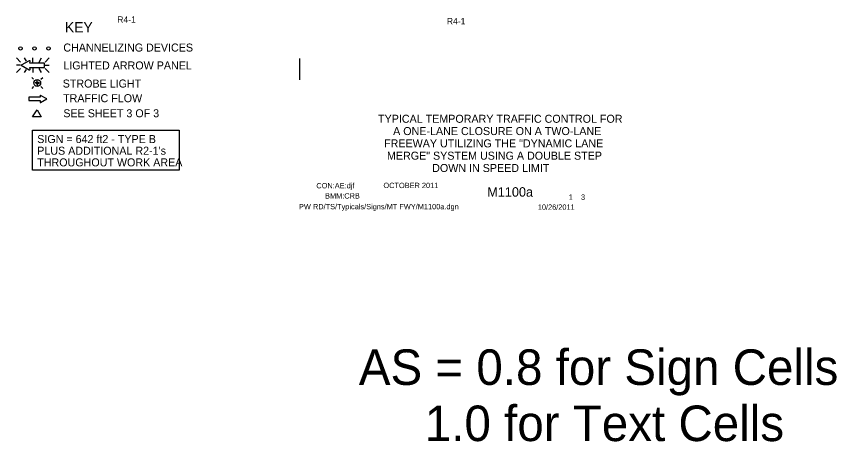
# Model space of a CAD drawing. Extents: x 15262 to 18126, y 1908 to 6555.
# Drawn here: x 15262 to 16214, y 1908 to 2402 of the extents above; entities that cross this region are included whole.
import ezdxf

# ---------------------------------------------------------------- set-up
doc = ezdxf.new("R2010")
doc.units = 0
for name, color, linetype in [('ALI_LEGAL_EX', 7, 'Continuous'), ('BORDER_SIGNAL_WO', 7, 'Continuous'), ('MT_SCRATCH_LEVEL_E', 7, 'Continuous'), ('TRAFFIC_SIGNS_PR', 7, 'Continuous'), ('TYPICAL_TEXT_DIMEN_EX', 7, 'Continuous'), ('TYPICAL_TEXT_DIMEN_PR', 7, 'Continuous')]:
    doc.layers.add(name, color=color, linetype=linetype)

msp = doc.modelspace()

# ---------------------------------------------------------------- linework, layer by layer
at = {"layer": 'ALI_LEGAL_EX'}
msp.add_lwpolyline([(15590.81, 2328.27), (15590.81, 2353.27)], dxfattribs=at)
at = {"layer": 'MT_SCRATCH_LEVEL_E'}
for p, q in [((15289.39, 2308.13), (15276.14, 2308.13)), ((15276.14, 2308.13), (15276.14, 2304.39)), ((15289.08, 2309.91), (15289.39, 2308.13)), ((15297, 2306.28), (15289.76, 2310.39)), ((15289.76, 2302.13), (15297, 2306.28)), ((15276.14, 2304.39), (15289.39, 2304.39)), ((15289.39, 2304.39), (15289.08, 2302.61))]:
    msp.add_line(p, q, dxfattribs=at)
for centre, start, end in [((15289.54, 2309.98), 60.42484, 189.96381), ((15289.54, 2302.54), 170.03619, 299.77312)]:
    msp.add_arc(centre, 0.463, start, end, dxfattribs=at)
at = {"layer": 'TRAFFIC_SIGNS_PR'}
for p, q in [((15261.64, 2353.83), (15266.58, 2348.9)), ((15273.41, 2350.01), (15271.2, 2353.84)), ((15280.73, 2348.9), (15280.73, 2353.84)), ((15287.96, 2348.9), (15290.81, 2353.84)), ((15294.88, 2348.9), (15299.81, 2353.84)), ((15266.58, 2345.35), (15261.64, 2345.35)), ((15294.88, 2345.35), (15299.81, 2345.35)), ((15261.64, 2336.86), (15266.58, 2341.79)), ((15271.16, 2336.85), (15273.27, 2340.52)), ((15280.73, 2341.79), (15280.73, 2336.85)), ((15290.86, 2336.85), (15288.01, 2341.79)), ((15294.88, 2341.79), (15299.81, 2336.85)), ((15281.6, 2329.06), (15279.56, 2331.09)), ((15285.88, 2324.78), (15283, 2324.78)), ((15285.88, 2324.78), (15285.88, 2327.66)), ((15285.88, 2324.78), (15285.88, 2320.84)), ((15285.88, 2324.78), (15288.76, 2324.78)), ((15290.16, 2329.06), (15292.19, 2331.09)), ((15281.6, 2320.5), (15279.56, 2318.47)), ((15292.19, 2318.47), (15290.16, 2320.5))]:
    msp.add_line(p, q, dxfattribs=at)
for points in [[(15276.65, 2350.62), (15267.36, 2345.35), (15276.66, 2340.02)], [(15277.53, 2340.65), (15277.13, 2342.92), (15294.14, 2342.92), (15294.14, 2347.72), (15277.13, 2347.72), (15277.53, 2350)]]:
    msp.add_lwpolyline(points, dxfattribs=at)
for centre, radius in [((15266.38, 2364.95), 2), ((15282.68, 2364.95), 2), ((15298.98, 2364.95), 2), ((15285.88, 2324.78), 3.94), ((15285.88, 2324.78), 1.28)]:
    msp.add_circle(centre, radius, dxfattribs=at)
for centre, radius, start, end in [((15276.94, 2350.1), 0.598, 350.73078, 118.89165), ((15276.94, 2340.55), 0.597, 241.48329, 9.95933)]:
    msp.add_arc(centre, radius, start, end, dxfattribs=at)
at = {"layer": 'TYPICAL_TEXT_DIMEN_EX'}
msp.add_lwpolyline([(15280.23, 2269.93), (15450.6, 2269.93), (15450.6, 2223.36), (15280.23, 2223.36)], close=True, dxfattribs=at)
at = {"layer": 'TYPICAL_TEXT_DIMEN_PR'}
msp.add_lwpolyline([(15280.34, 2285.58), (15285.8, 2293.46), (15290.42, 2285.58)], close=True, dxfattribs=at)

# ---------------------------------------------------------------- texts
at = {"layer": 'BORDER_SIGNAL_WO'}
for s, height, p in [('TYPICAL TEMPORARY TRAFFIC CONTROL FOR', 9.3, (15681.73, 2278.54)), ('A ONE-LANE CLOSURE ON A TWO-LANE', 9.3, (15699.24, 2264.24)), ('FREEWAY UTILIZING THE "DYNAMIC LANE', 9.3, (15688.74, 2249.94)), ('MERGE" SYSTEM USING A DOUBLE STEP ', 9.3, (15692.1, 2235.64)), ('DOWN IN SPEED LIMIT', 9.3, (15744.6, 2221.34)), ('CON:AE:djf  ', 6.2, (15610.05, 2202.35)), ('    OCTOBER 2011    ', 6.2, (15678.44, 2202.63)), ('    M1100a   ', 11, (15792.22, 2192.67)), ('BMM:CRB   ', 6.2, (15620.17, 2190.46)), (' 1    3 ', 6.2, (15900.81, 2188.99)), ('PW RD/TS/Typicals/Signs/MT FWY/M1100a.dgn      ', 6.2, (15589.92, 2178)), ('10/26/2011    ', 6.2, (15867.29, 2177.42)), ('AS = 0.8 for Sign Cells', 41.2877, (15659.37, 1973.92)), ('     1.0 for Text Cells', 41.2877, (15659.37, 1908.64))]:
    msp.add_text(s, height=height, dxfattribs=at).set_placement(p)
at = {"layer": 'TRAFFIC_SIGNS_PR'}
for p in [(15378.82, 2394.7), (15761.67, 2392.86)]:
    msp.add_text('R4-1', height=7.44, dxfattribs=at).set_placement(p)
at = {"layer": 'TYPICAL_TEXT_DIMEN_EX'}
for s, height, p in [('KEY', 12, (15318.11, 2383.5)), ('CHANNELIZING DEVICES', 9.3, (15316.16, 2361.28)), ('LIGHTED ARROW PANEL', 9.3, (15316.16, 2340.52)), ('STROBE LIGHT', 9.3, (15315.4, 2319.46)), ('TRAFFIC FLOW', 9.3, (15315.86, 2302.45)), ('SEE SHEET 3 OF 3', 9.3, (15316.16, 2284.93)), ('SIGN = 642 ft2 - TYPE B', 9.3, (15285.83, 2254.96)), ("PLUS ADDITIONAL R2-1's", 9.3, (15285.83, 2241.41)), ('THROUGHOUT WORK AREA', 9.3, (15285.83, 2227.86))]:
    msp.add_text(s, height=height, dxfattribs=at).set_placement(p)

doc.saveas('drawing.dxf')
